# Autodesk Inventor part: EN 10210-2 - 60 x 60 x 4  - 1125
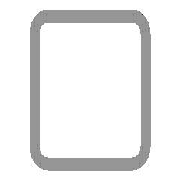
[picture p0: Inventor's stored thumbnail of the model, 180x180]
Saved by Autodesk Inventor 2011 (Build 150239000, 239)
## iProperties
IsCustomPart: 1
Created: 2010-02
Part Number: EN 10210-2 - 60 x 60 x 4  - 1125
Material: Steel, A36
Description: Tube 60*60*4
Document SubType Name: Modeling
Standard: DIN EN 10219-2
Designer: PC
Standard Revision: 1997
Standards Organization: DIN
Language: en-US
Size Designation: 60 x 60 x 4  - 1125
Categories: <MemberInstance><Categories><Category DisplayName="Structural Shapes" InternalName="089c4875-fa83-4c05-b084-43b9cc11f5ed" Mnemonic="GRDR"><CategoryParameter Dis
Stock Number: 60 x 60 x 4
Density: 7.85 g/cm^3
G_L: 1125.000 mm
Author: PC
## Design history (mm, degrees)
node "Start plane"
node "End plane"
sketch "Sketch"
  geometry: L1 (-30, -22)-(-30, 22); L2 (-22, 30)-(22, 30); L3 (30, 22)-(30, -22); L4 (22, -30)-(-22, -30); L5 (-22, 26)-(22, 26); L6 (26, 22)-(26, -22); L7 (22, -26)-(-22, -26); L8 (-26, -22)-(-26, 22); L9 (0, 37.102)-(0, -37.102) reference; L10 (-23.102, 0)-(23.102, 0) reference; A1 r 8 centre (-22, -22) between (-30, -22) and (-22, -30); A2 r 8 centre (-22, 22) between (-22, 30) and (-30, 22); A3 r 8 centre (22, 22) between (30, 22) and (22, 30); A4 r 8 centre (22, -22) between (22, -30) and (30, -22); A5 r 4 centre (-22, 22) between (-22, 26) and (-26, 22); A6 r 4 centre (22, 22) between (26, 22) and (22, 26); A7 r 4 centre (22, -22) between (22, -26) and (26, -22); A8 r 4 centre (-22, -22) between (-26, -22) and (-22, -26)
  constraints: 16 end point, 16 point on circle, 8 centre point, 8 tangent, 4 parallel, 3 equal radius, 2 perpendicular, 7 other
  dimensions: "d7" = 8 radius of A1 (= G_IR); "d10" = 60 distance between parallel lines of L2 L4 (= G_H); "d11" = 60 distance between parallel lines of L1 L3 (= G_W); "d12" = 4 distance between parallel lines of L3 L6 (= G_T); "d15" = 30 distance between parallel lines of L2 L10 (= 0.5 x d10); "d16" = 30 distance between parallel lines of L9 L3 (= 0.5 x d11)
extrude "Body" new body sketch "Sketch" stored distance "d3" = 1125 (= G_L); taper "d4" = 0 deg
node "Driven Length"
  sketch "Sketch3"
    geometry: L1 (0, 0)-(10, 0) reference
    constraints: 2 end point, 1 horizontal
  workplane "Work Plane3"
  sketch "Sketch4"
    geometry: L1 (-2, 0)-(12, 0) reference; L2 (-2, 1125)-(12, 1125) reference
    dimensions: "d18" = 1125 distance between parallel lines of L1 L2 (derived)
body "Solid1"
other parameters: "G_W" = 60 [user parameter; used in 1 equation term], "G_H" = 60 [user parameter; used in 1 equation term], "G_T" = 4 [user parameter; used in 1 equation term], "G_IR" = 8 [user parameter; used in 1 equation term], "G_L" = 1125 (= d18) [user parameter; used in 1 equation term], "G_OFFSET_START" = 0 [user parameter; used in 1 equation term], "G_OFFSET_END" = 0 [user parameter; used in 1 equation term], "d13" = 0 (computed from G_OFFSET_START), "d14" = 1125 (= G_OFFSET_END + B_L), "B_L" = 1125 [user parameter; used in 1 equation term], "d17" = 90 deg
